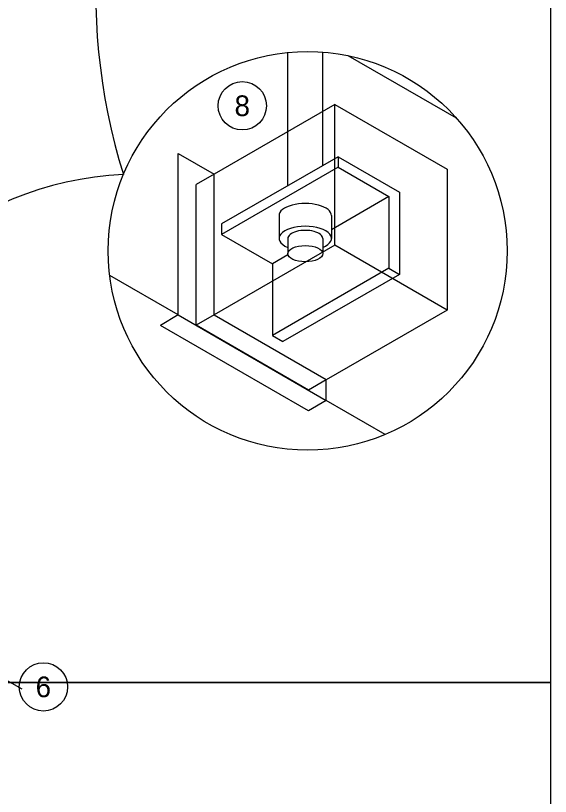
# Model space of a CAD drawing. Extents: x 10110.2 to 10159.4, y 10049.5 to 10140.5.
# Drawn here: x 10142.12 to 10159.36, y 10091.33 to 10116.52 of the extents above; entities that cross this region are included whole.
import ezdxf

# ---------------------------------------------------------------- set-up
doc = ezdxf.new("R2010")
doc.units = 0
for name, color, linetype in [('G-ANNO-SYMB', 7, 'Continuous'), ('G-DETL-GRID', 7, 'Continuous'), ('G-DETL-LINE', 7, 'Continuous'), ('G-DETL-TEXT', 7, 'Continuous')]:
    doc.layers.add(name, color=color, linetype=linetype)

msp = doc.modelspace()

# ---------------------------------------------------------------- linework, layer by layer
at = {"layer": 'G-ANNO-SYMB'}
for centre in [(10149.429, 10113.616), (10143.016, 10094.868)]:
    msp.add_circle(centre, 0.779, dxfattribs=at)
at = {"layer": 'G-DETL-GRID'}
for points in [[(10110.22, 10140.505), (10159.362, 10140.505), (10159.362, 10095.005), (10110.22, 10095.005)], [(10110.22, 10095.005), (10159.362, 10095.005), (10159.362, 10049.505), (10110.22, 10049.505)]]:
    msp.add_lwpolyline(points, close=True, dxfattribs=at)
at = {"layer": 'G-DETL-LINE'}
for p, q in [((10150.894, 10112.781), (10150.894, 10115.332)), ((10150.894, 10112.781), (10150.894, 10115.332)), ((10152.024, 10113.433), (10152.024, 10115.34)), ((10152.024, 10113.433), (10152.024, 10115.34)), ((10156.335, 10113.213), (10152.843, 10115.23)), ((10156.335, 10113.213), (10152.843, 10115.23)), ((10152.413, 10113.658), (10148.521, 10111.411)), ((10152.413, 10113.658), (10148.521, 10111.411)), ((10152.024, 10111.686), (10152.024, 10113.433)), ((10152.024, 10111.686), (10152.024, 10113.433)), ((10150.894, 10111.034), (10150.894, 10112.781)), ((10150.894, 10111.034), (10150.894, 10112.781)), ((10147.365, 10106.866), (10147.365, 10112.077)), ((10147.365, 10112.077), (10148.52, 10111.41)), ((10147.365, 10106.866), (10147.365, 10112.077)), ((10147.365, 10112.077), (10148.52, 10111.41)), ((10152.519, 10111.972), (10148.761, 10109.802)), ((10152.519, 10111.972), (10148.761, 10109.802)), ((10152.519, 10111.972), (10154.497, 10110.829)), ((10152.519, 10111.972), (10152.519, 10111.631)), ((10152.519, 10111.972), (10154.497, 10110.829)), ((10152.519, 10111.972), (10152.519, 10111.631)), ((10152.519, 10111.631), (10148.761, 10109.461)), ((10152.519, 10111.631), (10148.761, 10109.461)), ((10152.519, 10111.631), (10154.156, 10110.685)), ((10152.519, 10111.631), (10154.156, 10110.685)), ((10148.521, 10111.411), (10147.943, 10111.077)), ((10148.521, 10111.411), (10147.943, 10111.077)), ((10148.521, 10106.867), (10148.521, 10111.411)), ((10148.521, 10106.867), (10148.521, 10111.411)), ((10147.943, 10106.533), (10147.943, 10111.077)), ((10147.943, 10106.533), (10147.943, 10111.077)), ((10154.156, 10110.685), (10152.306, 10109.617)), ((10154.156, 10110.685), (10152.306, 10109.617)), ((10154.156, 10110.685), (10154.156, 10108.373)), ((10154.156, 10110.685), (10154.156, 10108.373)), ((10154.497, 10110.829), (10154.497, 10108.176)), ((10154.497, 10110.829), (10154.497, 10108.176)), ((10150.612, 10110.073), (10150.612, 10109.336)), ((10150.612, 10110.073), (10150.612, 10109.336)), ((10152.306, 10110.073), (10152.306, 10109.336)), ((10152.306, 10110.073), (10152.306, 10109.336)), ((10148.761, 10109.802), (10148.761, 10109.461)), ((10148.761, 10109.802), (10148.761, 10109.461)), ((10148.761, 10109.461), (10150.399, 10108.516)), ((10148.761, 10109.461), (10150.399, 10108.516)), ((10150.894, 10109.336), (10150.894, 10108.845)), ((10150.894, 10109.336), (10150.894, 10108.845)), ((10152.024, 10109.336), (10152.024, 10108.845)), ((10152.024, 10109.336), (10152.024, 10108.845)), ((10152.413, 10109.114), (10148.521, 10106.867)), ((10152.413, 10109.114), (10148.521, 10106.867)), ((10150.901, 10108.805), (10150.399, 10108.516)), ((10150.901, 10108.805), (10150.399, 10108.516)), ((10150.399, 10108.516), (10150.399, 10106.204)), ((10150.399, 10108.516), (10150.399, 10106.204)), ((10154.156, 10108.373), (10150.399, 10106.204)), ((10154.156, 10108.373), (10150.399, 10106.204)), ((10154.156, 10108.373), (10154.497, 10108.176)), ((10154.156, 10108.373), (10154.497, 10108.176)), ((10147.365, 10106.866), (10145.159, 10108.14)), ((10147.365, 10106.866), (10145.159, 10108.14)), ((10154.497, 10108.176), (10150.74, 10106.007)), ((10154.497, 10108.176), (10150.74, 10106.007)), ((10147.365, 10106.866), (10146.787, 10106.532)), ((10147.365, 10106.866), (10146.787, 10106.532)), ((10147.365, 10106.866), (10152.136, 10104.112)), ((10147.365, 10106.866), (10152.136, 10104.112)), ((10148.521, 10106.867), (10147.943, 10106.533)), ((10148.521, 10106.867), (10147.943, 10106.533)), ((10152.137, 10104.777), (10148.521, 10106.865)), ((10152.137, 10104.777), (10148.521, 10106.865)), ((10156.029, 10107.026), (10152.135, 10104.778)), ((10156.029, 10107.026), (10152.135, 10104.778)), ((10151.558, 10103.778), (10146.787, 10106.532)), ((10151.558, 10103.778), (10146.787, 10106.532)), ((10151.559, 10104.445), (10147.943, 10106.533)), ((10151.559, 10104.445), (10147.943, 10106.533)), ((10150.399, 10106.204), (10150.74, 10106.007)), ((10150.399, 10106.204), (10150.74, 10106.007)), ((10152.135, 10104.778), (10151.559, 10104.445)), ((10152.135, 10104.778), (10151.559, 10104.445)), ((10152.136, 10104.112), (10152.136, 10104.778)), ((10152.136, 10104.112), (10152.136, 10104.778)), ((10152.136, 10104.112), (10151.558, 10103.778)), ((10152.136, 10104.112), (10151.558, 10103.778)), ((10154.038, 10103.014), (10152.136, 10104.112)), ((10154.038, 10103.014), (10152.136, 10104.112))]:
    msp.add_line(p, q, dxfattribs=at)
msp.add_lwpolyline([(10156.029, 10107.026), (10152.413, 10109.114), (10152.413, 10113.658), (10156.029, 10111.57)], close=True, dxfattribs=at)
msp.add_lwpolyline([(10156.029, 10107.026), (10152.413, 10109.114), (10152.413, 10113.658), (10156.029, 10111.57)], close=True, dxfattribs=at)
for centre, major_axis, start_param, end_param in [((10151.459, 10110.073), (-0.847, 0), 3.137491, 6.287287), ((10151.459, 10110.073), (-0.847, 0), 3.137491, 6.287287), ((10151.459, 10109.336), (-0.847, 0), 2.300516, 7.124262), ((10151.459, 10109.336), (-0.847, 0), 2.300516, 7.124262), ((10151.459, 10109.336), (-0.565, 0), 3.137491, 6.287287), ((10151.459, 10109.336), (-0.565, 0), 3.137491, 6.287287)]:
    msp.add_ellipse(centre, major_axis=major_axis, ratio=0.460797, start_param=start_param, end_param=end_param, dxfattribs=at)
msp.add_ellipse((10151.459, 10108.845), major_axis=(-0.565, 0), ratio=0.460797, dxfattribs=at)
msp.add_ellipse((10151.459, 10108.845), major_axis=(-0.565, 0), ratio=0.460797, dxfattribs=at)
at = {"layer": 'G-DETL-TEXT'}
msp.add_line((10142.329, 10094.794), (10140.378, 10095.896), dxfattribs=at)
msp.add_circle((10151.536, 10108.934), 6.432, dxfattribs=at)
for centre, radius, start, end in [((10164.714, 10117.308), 20.014, 151.243, 197.1832), ((10164.714, 10117.308), 20.014, 151.243, 197.1832), ((10146.103, 10100.578), 10.828, 92.6951, 169.6737), ((10146.103, 10100.578), 10.828, 92.6951, 169.6737)]:
    msp.add_arc(centre, radius, start, end, dxfattribs=at)

# ---------------------------------------------------------------- texts
at = {"layer": 'G-ANNO-SYMB'}
for s, p in [('8', (10149.179, 10113.283)), ('6', (10142.766, 10094.534))]:
    msp.add_text(s, height=0.667, dxfattribs=at).set_placement(p)

doc.saveas('drawing.dxf')
